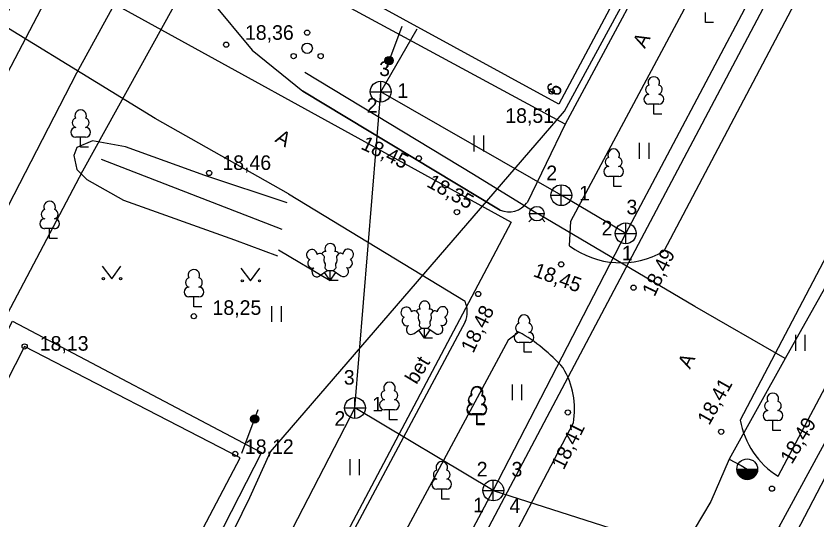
# Model space of a CAD drawing. Extents: x 713540 to 713867, y 6589774 to 6590061.
# Drawn here: x 713737.83 to 713776.25, y 6589992.37 to 6590016.58 of the extents above; entities that cross this region are included whole.
import ezdxf

# ---------------------------------------------------------------- set-up
doc = ezdxf.new("R2010")
doc.units = 0
for name, color, linetype in [('HALJASTUS', 7, 'Continuous'), ('HOONE', 7, 'Continuous'), ('HOONEDET', 7, 'Continuous'), ('KKAEV', 7, 'Continuous'), ('KORGUS', 7, 'Continuous'), ('KTRASS', 7, 'Continuous'), ('MPKAABEL', 7, 'Continuous'), ('PUU', 7, 'Continuous'), ('SIOHULIIN', 7, 'Continuous'), ('SITRASS', 7, 'Continuous'), ('TEE', 7, 'Continuous'), ('TORU NR', 7, 'Continuous'), ('TTRASS', 7, 'Continuous'), ('VKAEV', 7, 'Continuous'), ('VTRASS', 7, 'Continuous'), ('Слой 1', 7, 'Continuous')]:
    doc.layers.add(name, color=color, linetype=linetype)

msp = doc.modelspace()

# ---------------------------------------------------------------- linework, layer by layer
at = {"layer": 'HALJASTUS'}
for p, q in [((713759.827, 6590010.839), (713759.827, 6590010.078)), ((713760.282, 6590010.839), (713760.282, 6590010.078)), ((713767.765, 6590010.481), (713767.765, 6590009.72)), ((713768.22, 6590010.481), (713768.22, 6590009.72)), ((713741.967, 6590004.567), (713742.43, 6590003.96)), ((713742.43, 6590003.96), (713742.876, 6590004.567)), ((713748.637, 6590004.467), (713749.1, 6590003.86)), ((713749.1, 6590003.86), (713749.546, 6590004.467)), ((713750.106, 6590002.644), (713750.106, 6590001.883)), ((713750.561, 6590002.644), (713750.561, 6590001.883)), ((713775.264, 6590001.264), (713775.264, 6590000.503)), ((713775.719, 6590001.264), (713775.719, 6590000.503)), ((713761.657, 6589998.886), (713761.657, 6589998.125)), ((713762.112, 6589998.886), (713762.112, 6589998.125)), ((713753.865, 6589995.292), (713753.865, 6589994.531)), ((713754.32, 6589995.292), (713754.32, 6589994.531))]:
    msp.add_line(p, q, dxfattribs=at)
for points in [[(713741.51, 6590010.58), (713740.75, 6590010.26), (713740.61, 6590009.88), (713740.75, 6590009.21), (713741.23, 6590008.73), (713742.99, 6590007.73), (713748.33, 6590005.83), (713750.392, 6590005.054)], [(713750.851, 6590007.606), (713746.9, 6590008.92), (713743.09, 6590010.3), (713741.51, 6590010.58)], [(713750.621, 6590006.329), (713741.94, 6590009.69)], [(713750.444, 6590005.347), (713752.927, 6590003.875)]]:
    msp.add_lwpolyline(points, dxfattribs=at)
for centre, radius in [((713751.817, 6590015.778), 0.125), ((713751.817, 6590015.028), 0.25), ((713751.167, 6590014.653), 0.125), ((713752.467, 6590014.653), 0.125), ((713742.029, 6590003.96), 0.055), ((713742.858, 6590003.96), 0.055), ((713748.699, 6590003.86), 0.055), ((713749.528, 6590003.86), 0.055)]:
    msp.add_circle(centre, radius, dxfattribs=at)
at = {"layer": 'HOONE'}
for points in [[(713723.34, 6589972.07), (713723.61, 6589972.88), (713723.79, 6589973.29), (713724.07, 6589973.48), (713724.62, 6589973.75), (713731.173, 6589976.164), (713742.67, 6589980.4), (713749.07, 6589993.45), (713750.05, 6589995.65), (713764.17, 6590012), (713775.83, 6590033.48), (713771.45, 6590035.85), (713767.347, 6590038.074), (713765.461, 6590039.097), (713761.12, 6590041.45), (713760.38, 6590041.94), (713759.89, 6590042.09), (713754.46, 6590032.78), (713755.34, 6590032.31)], [(713759.88, 6590040.7), (713774.663, 6590032.532), (713763.899, 6590012.346), (713748.96, 6590020.53), (713759.88, 6590040.7)], [(713729.99, 6589999.65), (713748.41, 6590034.82)], [(713748.594, 6589995.354), (713738.24, 6590000.71), (713731.11, 6589986.72), (713741.204, 6589981.346), (713744.152, 6589986.933), (713744.399, 6589986.803), (713745.932, 6589989.695), (713745.679, 6589989.828), (713748.594, 6589995.354)]]:
    msp.add_lwpolyline(points, dxfattribs=at)
at = {"layer": 'HOONEDET'}
for points in [[(713764.214, 6590011.385), (713748.01, 6590020.15), (713748.17, 6590020.34), (713748.23, 6590020.65), (713753, 6590029.57)], [(713745.35, 6589987.248), (713741.618, 6589979.947), (713729.646, 6589986.262), (713737.66, 6590001.929), (713749.627, 6589995.616), (713745.981, 6589988.482)]]:
    msp.add_lwpolyline(points, dxfattribs=at)
at = {"layer": 'KKAEV'}
for p, q in [((713755.348, 6590012.443), (713755.348, 6590013.443)), ((713754.848, 6590012.943), (713755.848, 6590012.943)), ((713764.023, 6590007.47), (713764.023, 6590008.47)), ((713763.523, 6590007.97), (713764.523, 6590007.97)), ((713767.114, 6590005.64), (713767.114, 6590006.64)), ((713766.614, 6590006.14), (713767.614, 6590006.14)), ((713754.114, 6589997.254), (713754.114, 6589998.254)), ((713753.614, 6589997.754), (713754.614, 6589997.754)), ((713760.755, 6589993.294), (713760.755, 6589994.294)), ((713760.255, 6589993.794), (713761.255, 6589993.794))]:
    msp.add_line(p, q, dxfattribs=at)
for centre in [(713755.348, 6590012.943), (713764.023, 6590007.97), (713767.114, 6590006.14), (713754.114, 6589997.754), (713760.755, 6589993.794)]:
    msp.add_circle(centre, 0.5, dxfattribs=at)
at = {"layer": 'KORGUS'}
for centre in [(713747.93, 6590015.2), (713763.56, 6590012.95), (713757.18, 6590009.74), (713747.11, 6590009.04), (713759.01, 6590007.16), (713764.02, 6590004.65), (713767.49, 6590003.53), (713760.03, 6590003.23), (713746.37, 6590002.16), (713738.25, 6590000.71), (713764.34, 6589997.54), (713771.7, 6589996.61), (713748.36, 6589995.55), (713774.14, 6589993.88)]:
    msp.add_circle(centre, 0.125, dxfattribs=at)
at = {"layer": 'KTRASS'}
for p, q in [((713767.114, 6590006.14), (713787.107, 6590043.801)), ((713755.348, 6590012.943), (713757.104, 6590015.958)), ((713754.114, 6589997.754), (713755.348, 6590012.943)), ((713764.023, 6590007.97), (713755.348, 6590012.943)), ((713767.114, 6590006.14), (713764.023, 6590007.97)), ((713760.755, 6589993.794), (713767.114, 6590006.14)), ((713754.114, 6589997.754), (713749.216, 6589988.299)), ((713760.755, 6589993.794), (713754.114, 6589997.754)), ((713746.283, 6589966.793), (713760.755, 6589993.794)), ((713760.755, 6589993.794), (713773.086, 6589989.851))]:
    msp.add_line(p, q, dxfattribs=at)
at = {"layer": 'MPKAABEL'}
for points in [[(713796.776, 6590060.636), (713793.419, 6590054.295), (713774.719, 6590018.872), (713756.007, 6589983.478), (713738.52, 6589950.8), (713723.469, 6589921.84)], [(713734.86, 6589982.939), (713729.11, 6589985.97), (713735.68, 6589998.99), (713741.04, 6590009.14), (713752.51, 6590029.86)]]:
    msp.add_lwpolyline(points, dxfattribs=at)
at = {"layer": 'PUU'}
for p, q in [((713770.951, 6590016.264), (713770.951, 6590016.739)), ((713771.331, 6590016.264), (713770.951, 6590016.264)), ((713768.707, 6590012.342), (713768.227, 6590012.342)), ((713768.467, 6590011.867), (713768.467, 6590012.342)), ((713768.847, 6590011.867), (713768.467, 6590011.867)), ((713741.18, 6590010.755), (713740.7, 6590010.755)), ((713740.94, 6590010.28), (713740.94, 6590010.755)), ((713741.32, 6590010.28), (713740.94, 6590010.28)), ((713766.778, 6590008.869), (713766.298, 6590008.869)), ((713766.538, 6590008.394), (713766.538, 6590008.869)), ((713766.918, 6590008.394), (713766.538, 6590008.394)), ((713739.69, 6590006.365), (713739.21, 6590006.365)), ((713739.45, 6590005.89), (713739.45, 6590006.365)), ((713739.83, 6590005.89), (713739.45, 6590005.89)), ((713752.417, 6590004.095), (713752.777, 6590004.35)), ((713752.777, 6590004.35), (713753.072, 6590004.35)), ((713752.927, 6590003.875), (713752.927, 6590004.35)), ((713753.072, 6590004.35), (713753.432, 6590004.105)), ((713752.927, 6590003.875), (713752.652, 6590004.26)), ((713752.927, 6590003.875), (713753.197, 6590004.265)), ((713753.307, 6590003.875), (713752.927, 6590003.875)), ((713746.62, 6590003.085), (713746.14, 6590003.085)), ((713746.38, 6590002.61), (713746.38, 6590003.085)), ((713746.76, 6590002.61), (713746.38, 6590002.61)), ((713756.95, 6590001.329), (713757.31, 6590001.584)), ((713757.46, 6590001.109), (713757.185, 6590001.494)), ((713757.31, 6590001.584), (713757.605, 6590001.584)), ((713757.46, 6590001.109), (713757.46, 6590001.584)), ((713757.46, 6590001.109), (713757.73, 6590001.499)), ((713757.605, 6590001.584), (713757.965, 6590001.339)), ((713757.84, 6590001.109), (713757.46, 6590001.109)), ((713762.472, 6590000.902), (713761.992, 6590000.902)), ((713762.232, 6590000.427), (713762.232, 6590000.902)), ((713762.612, 6590000.427), (713762.232, 6590000.427)), ((713756.01, 6589997.665), (713755.53, 6589997.665)), ((713755.77, 6589997.19), (713755.77, 6589997.665)), ((713760.2, 6589997.425), (713759.72, 6589997.425)), ((713760.216, 6589997.47), (713759.736, 6589997.47)), ((713759.96, 6589996.95), (713759.96, 6589997.425)), ((713759.976, 6589996.995), (713759.976, 6589997.47)), ((713756.15, 6589997.19), (713755.77, 6589997.19)), ((713774.424, 6589997.15), (713773.944, 6589997.15)), ((713774.184, 6589996.675), (713774.184, 6589997.15)), ((713760.34, 6589996.95), (713759.96, 6589996.95)), ((713760.356, 6589996.995), (713759.976, 6589996.995)), ((713774.564, 6589996.675), (713774.184, 6589996.675)), ((713758.52, 6589993.854), (713758.04, 6589993.854)), ((713758.28, 6589993.379), (713758.28, 6589993.854)), ((713758.66, 6589993.379), (713758.28, 6589993.379))]:
    msp.add_line(p, q, dxfattribs=at)
for points in [[(713752.514, 6590005.162), (713752.617, 6590005.06), (713752.632, 6590005.03), (713752.632, 6590004.975), (713752.617, 6590004.885), (713752.617, 6590004.84), (713752.637, 6590004.76), (713752.677, 6590004.67), (713752.687, 6590004.625), (713752.682, 6590004.58), (713752.667, 6590004.515), (713752.667, 6590004.485), (713752.687, 6590004.445), (713752.712, 6590004.415), (713752.777, 6590004.35)], [(713753.331, 6590005.176), (713753.237, 6590005.06), (713753.222, 6590005.03), (713753.222, 6590004.975), (713753.237, 6590004.885), (713753.242, 6590004.84), (713753.222, 6590004.76), (713753.182, 6590004.67), (713753.172, 6590004.625), (713753.177, 6590004.58), (713753.192, 6590004.515), (713753.192, 6590004.485), (713753.172, 6590004.445), (713753.147, 6590004.415), (713753.077, 6590004.35)], [(713757.048, 6590002.396), (713757.15, 6590002.294), (713757.165, 6590002.264), (713757.165, 6590002.209), (713757.15, 6590002.119), (713757.15, 6590002.074), (713757.17, 6590001.994), (713757.21, 6590001.904), (713757.22, 6590001.859), (713757.215, 6590001.814), (713757.2, 6590001.749), (713757.2, 6590001.719), (713757.22, 6590001.679), (713757.245, 6590001.649), (713757.31, 6590001.584)], [(713757.864, 6590002.41), (713757.77, 6590002.294), (713757.755, 6590002.264), (713757.755, 6590002.209), (713757.77, 6590002.119), (713757.775, 6590002.074), (713757.755, 6590001.994), (713757.715, 6590001.904), (713757.705, 6590001.859), (713757.71, 6590001.814), (713757.725, 6590001.749), (713757.725, 6590001.719), (713757.705, 6590001.679), (713757.68, 6590001.649), (713757.61, 6590001.584)]]:
    msp.add_lwpolyline(points, dxfattribs=at)
for centre, radius, start, end in [((713768.467, 6590013.387), 0.277, 332.5799, 207.4201), ((713768.297, 6590013.039), 0.233, 109.0217, 253.1415), ((713768.637, 6590013.039), 0.233, 286.8508, 70.9859), ((713768.229, 6590012.579), 0.238, 90.0016, 269.3953), ((713768.704, 6590012.579), 0.238, 270.6047, 89.9984), ((713740.94, 6590011.8), 0.277, 332.5799, 207.4201), ((713740.77, 6590011.453), 0.233, 109.0217, 253.1415), ((713741.11, 6590011.453), 0.233, 286.8508, 70.9859), ((713740.703, 6590010.992), 0.238, 90.0016, 269.3953), ((713741.177, 6590010.992), 0.238, 270.6047, 89.9984), ((713766.538, 6590009.914), 0.277, 332.5799, 207.4201), ((713766.368, 6590009.567), 0.233, 109.0217, 253.1415), ((713766.708, 6590009.567), 0.233, 286.8508, 70.9859), ((713766.3, 6590009.107), 0.238, 90.0016, 269.3953), ((713766.775, 6590009.107), 0.238, 270.6047, 89.9984), ((713739.45, 6590007.41), 0.277, 332.5799, 207.4201), ((713739.28, 6590007.063), 0.233, 109.0217, 253.1415), ((713739.62, 6590007.063), 0.233, 286.8508, 70.9859), ((713739.213, 6590006.602), 0.238, 90.0016, 269.3953), ((713739.687, 6590006.602), 0.238, 270.6047, 89.9984), ((713752.927, 6590005.395), 0.256, 90.0013, 211.0159), ((713752.927, 6590005.395), 0.256, 328.9841, 89.9987), ((713752.043, 6590005.112), 0.256, 125.5389, 246.5536), ((713752.043, 6590005.112), 0.256, 4.5218, 125.5364), ((713752.43, 6590004.979), 0.202, 65.2382, 130.7412), ((713752.689, 6590005.063), 0.202, 84.7965, 150.2995), ((713753.164, 6590005.063), 0.202, 34.3857, 95.2035), ((713753.403, 6590004.988), 0.202, 50.3173, 111.1351), ((713753.787, 6590005.128), 0.256, 55.522, 176.5367), ((713753.787, 6590005.128), 0.256, 294.5049, 55.5195), ((713752.072, 6590004.695), 0.224, 125.4667, 288.5349), ((713753.767, 6590004.711), 0.224, 252.5235, 55.5918), ((713746.38, 6590004.13), 0.277, 332.5799, 207.4201), ((713752.281, 6590004.289), 0.237, 125.5377, 305.5366), ((713753.565, 6590004.301), 0.237, 235.5219, 55.5208), ((713746.21, 6590003.783), 0.233, 109.0217, 253.1415), ((713746.55, 6590003.783), 0.233, 286.8508, 70.9859), ((713746.143, 6590003.322), 0.238, 90.0016, 269.3953), ((713746.617, 6590003.322), 0.238, 270.6047, 89.9984), ((713757.46, 6590002.629), 0.256, 90.0013, 211.0159), ((713757.46, 6590002.629), 0.256, 328.9841, 89.9987), ((713756.577, 6590002.346), 0.256, 125.5389, 246.5536), ((713756.577, 6590002.346), 0.256, 4.5218, 125.5364), ((713756.963, 6590002.213), 0.202, 65.2382, 130.7412), ((713757.223, 6590002.296), 0.202, 84.7965, 150.2995), ((713757.698, 6590002.296), 0.202, 34.3857, 95.2035), ((713757.937, 6590002.222), 0.202, 50.3173, 111.1351), ((713758.321, 6590002.362), 0.256, 55.522, 176.5367), ((713758.321, 6590002.362), 0.256, 294.5049, 55.5195), ((713756.605, 6590001.928), 0.224, 125.4667, 288.5349), ((713758.3, 6590001.944), 0.224, 252.5235, 55.5918), ((713762.232, 6590001.947), 0.277, 332.5799, 207.4201), ((713756.814, 6590001.523), 0.237, 125.5377, 305.5366), ((713758.098, 6590001.535), 0.237, 235.5219, 55.5208), ((713762.062, 6590001.6), 0.233, 109.0217, 253.1415), ((713762.402, 6590001.6), 0.233, 286.8508, 70.9859), ((713761.995, 6590001.14), 0.238, 90.0016, 269.3953), ((713762.47, 6590001.14), 0.238, 270.6047, 89.9984), ((713755.77, 6589998.71), 0.277, 332.5799, 207.4201), ((713755.6, 6589998.363), 0.233, 109.0217, 253.1415), ((713755.94, 6589998.363), 0.233, 286.8508, 70.9859), ((713759.96, 6589998.47), 0.277, 332.5799, 207.4201), ((713759.976, 6589998.515), 0.277, 332.5799, 207.4201), ((713759.79, 6589998.123), 0.233, 109.0217, 253.1415), ((713759.806, 6589998.167), 0.233, 109.0217, 253.1415), ((713760.13, 6589998.123), 0.233, 286.8508, 70.9859), ((713760.146, 6589998.167), 0.233, 286.8508, 70.9859), ((713774.184, 6589998.195), 0.277, 332.5799, 207.4201), ((713755.533, 6589997.902), 0.238, 90.0016, 269.3953), ((713756.007, 6589997.902), 0.238, 270.6047, 89.9984), ((713759.723, 6589997.662), 0.238, 90.0016, 269.3953), ((713759.738, 6589997.707), 0.238, 90.0016, 269.3953), ((713760.197, 6589997.662), 0.238, 270.6047, 89.9984), ((713760.213, 6589997.707), 0.238, 270.6047, 89.9984), ((713774.014, 6589997.848), 0.233, 109.0217, 253.1415), ((713774.354, 6589997.848), 0.233, 286.8508, 70.9859), ((713773.947, 6589997.388), 0.238, 90.0016, 269.3953), ((713774.422, 6589997.388), 0.238, 270.6047, 89.9984), ((713758.28, 6589994.899), 0.277, 332.5799, 207.4201), ((713758.11, 6589994.552), 0.233, 109.0217, 253.1415), ((713758.45, 6589994.552), 0.233, 286.8508, 70.9859), ((713758.043, 6589994.092), 0.238, 90.0016, 269.3953), ((713758.518, 6589994.092), 0.238, 270.6047, 89.9984)]:
    msp.add_arc(centre, radius, start, end, dxfattribs=at)
at = {"layer": 'SIOHULIIN'}
for p, q in [((713756.364, 6590016.07), (713755.577, 6590013.972)), ((713748.682, 6589995.588), (713749.469, 6589997.686))]:
    msp.add_line(p, q, dxfattribs=at)
for centre, radius in [((713755.752, 6590014.437), 0.199), ((713755.752, 6590014.437), 0.19), ((713755.752, 6590014.437), 0.18), ((713755.752, 6590014.437), 0.171), ((713755.752, 6590014.437), 0.162), ((713755.752, 6590014.437), 0.152), ((713755.752, 6590014.437), 0.143), ((713755.752, 6590014.437), 0.133), ((713755.752, 6590014.437), 0.124), ((713755.752, 6590014.437), 0.114), ((713755.752, 6590014.437), 0.105), ((713755.752, 6590014.437), 0.0953), ((713755.752, 6590014.437), 0.0858), ((713755.752, 6590014.437), 0.0763), ((713755.752, 6590014.437), 0.0669), ((713755.752, 6590014.437), 0.0574), ((713755.752, 6590014.437), 0.0479), ((713755.752, 6590014.437), 0.0385), ((713755.752, 6590014.437), 0.029), ((713755.752, 6590014.437), 0.0195), ((713755.752, 6590014.437), 0.0101), ((713755.752, 6590014.437), 0.00061), ((713749.295, 6589997.222), 0.199), ((713749.295, 6589997.222), 0.19), ((713749.295, 6589997.222), 0.18), ((713749.295, 6589997.222), 0.171), ((713749.295, 6589997.222), 0.162), ((713749.295, 6589997.222), 0.152), ((713749.295, 6589997.222), 0.143), ((713749.295, 6589997.222), 0.133), ((713749.295, 6589997.222), 0.124), ((713749.295, 6589997.222), 0.114), ((713749.295, 6589997.222), 0.105), ((713749.295, 6589997.222), 0.0953), ((713749.295, 6589997.222), 0.0858), ((713749.295, 6589997.222), 0.0763), ((713749.295, 6589997.222), 0.0669), ((713749.295, 6589997.222), 0.0574), ((713749.295, 6589997.222), 0.0479), ((713749.295, 6589997.222), 0.0385), ((713749.295, 6589997.222), 0.029), ((713749.295, 6589997.222), 0.0195), ((713749.295, 6589997.222), 0.0101), ((713749.295, 6589997.222), 0.00061)]:
    msp.add_circle(centre, radius, dxfattribs=at)
at = {"layer": 'SITRASS'}
msp.add_lwpolyline([(713758.037, 6589957.335), (713761.879, 6589966.052), (713768.07, 6589978.18), (713774.37, 6589989.97), (713787.88, 6590015.87), (713811.74, 6590060.636)], dxfattribs=at)
at = {"layer": 'TEE'}
for points in [[(713750.927, 6590008.03), (713744.522, 6590011.657), (713734.435, 6590017.847), (713736.903, 6590022.368), (713743.125, 6590024.07), (713753.784, 6590044.184), (713757.249, 6590042.712), (713751.718, 6590032.993), (713753.469, 6590031.801), (713752.46, 6590029.762), (713751.314, 6590029.769), (713746.538, 6590021.024), (713746.409, 6590019.015), (713747.208, 6590017.314), (713749.179, 6590014.931), (713751.617, 6590012.967), (713761.092, 6590007.257)], [(713764.413, 6590005.547), (713764.486, 6590006.722), (713773.085, 6590022.835), (713783.408, 6590042.298)], [(713786.811, 6590039.201), (713779.489, 6590025.296), (713768.944, 6590005.279)], [(713792.829, 6590035.544), (713785.752, 6590022.212), (713772.613, 6589997.173)], [(713774.429, 6589994.473), (713796.161, 6590035.494)], [(713775.63, 6590032.655), (713764.214, 6590011.385), (713762.375, 6590007.609)], [(713761.092, 6590007.257), (713751.617, 6590012.967)], [(713750.927, 6590008.03), (713759.401, 6590002.879)], [(713759.411, 6590001.885), (713751.374, 6589986.858), (713750.166, 6589986.221), (713746.304, 6589988.311)], [(713761.987, 6590001.396), (713761.468, 6590001.011), (713752.66, 6589984.637)], [(713750.834, 6589971.193), (713761.766, 6589991.596), (713764.601, 6589997.036)]]:
    msp.add_lwpolyline(points, dxfattribs=at)
for centre, radius, start, end in [((713761.508, 6590008.255), 1.081, 247.3703, 323.2856), ((713766.882, 6590008.848), 4.122, 233.2053, 300.0107), ((713758.21, 6590002.369), 1.295, 338.0567, 23.1742), ((713758.276, 6589994.66), 7.691, 40.7145, 61.1472), ((713760.873, 6589997.703), 3.787, 349.8535, 31.4041), ((713776.602, 6589997.895), 4.054, 190.2638, 237.5847)]:
    msp.add_arc(centre, radius, start, end, dxfattribs=at)
at = {"layer": 'TTRASS'}
msp.add_lwpolyline([(713750, 6590030.71), (713740.74, 6590013.84), (713731.96, 6589996.83)], dxfattribs=at)
at = {"layer": 'VKAEV'}
for p, q in [((713762.499, 6590007.086), (713763.199, 6590007.086)), ((713762.602, 6590006.839), (713762.462, 6590006.699)), ((713763.096, 6590006.839), (713763.236, 6590006.699)), ((713772.451, 6589994.81), (713773.451, 6589994.81))]:
    msp.add_line(p, q, dxfattribs=at)
for centre, radius in [((713762.849, 6590007.086), 0.35), ((713772.951, 6589994.81), 0.5)]:
    msp.add_circle(centre, radius, dxfattribs=at)
for radius in [0.483, 0.468, 0.45, 0.435, 0.418, 0.403, 0.386, 0.371, 0.354, 0.339, 0.321, 0.306, 0.289, 0.274, 0.257, 0.242, 0.224, 0.209, 0.192, 0.177, 0.16, 0.145, 0.127, 0.112, 0.0951, 0.0801, 0.0628, 0.0478, 0.0328, 0.0178]:
    msp.add_arc((713772.951, 6589994.81), radius, 180, 0, dxfattribs=at)
at = {"layer": 'VTRASS'}
for points in [[(713786.9, 6590022.053), (713786.663, 6590021.42), (713779.918, 6590009.263), (713774.768, 6590000.13), (713772.089, 6589995.293), (713771.2, 6589993.262), (713769.595, 6589990.576), (713766.999, 6589985.749), (713760.969, 6589973.854), (713754.105, 6589960.72), (713753.933, 6589960.165), (713750.695, 6589954.533), (713746.011, 6589945.782), (713740.356, 6589934.918), (713733.16, 6589921.546), (713727.052, 6589912.116), (713721.352, 6589902.724), (713721.093, 6589902.329)], [(713774.768, 6590000.13), (713770.428, 6590002.625), (713762.925, 6590007.061), (713762.849, 6590007.086), (713759.809, 6590008.971), (713751.705, 6590013.861)], [(713772.089, 6589995.293), (713772.662, 6589994.986), (713772.949, 6589994.813)]]:
    msp.add_lwpolyline(points, dxfattribs=at)
at = {"layer": 'Слой 1'}
for points in [[(713800.41, 6589978.59), (713774.49, 6589992.04), (713800.2, 6590039.34), (713825.44, 6590025.65), (713821.32, 6590016.86), (713835.15, 6590009.97), (713817.82, 6589976.66), (713803.26, 6589984.22)], [(713738.74, 6590019.27), (713761.62, 6590006.68), (713742.5, 6589970.55), (713719.65, 6589982.59)]]:
    msp.add_lwpolyline(points, close=True, dxfattribs=at)

# ---------------------------------------------------------------- texts
at = {"layer": 'HOONE'}
msp.add_text('6', height=0.7, rotation=61.9613, dxfattribs=at).set_placement((713763.865, 6590012.664))
at = {"layer": 'HOONEDET'}
msp.add_text('bet', height=0.7, rotation=58.8475, dxfattribs=at).set_placement((713757.072, 6589998.846))
at = {"layer": 'KORGUS'}
for s, p in [('18,36', (713748.83, 6590015.435)), ('18,51', (713761.332, 6590011.445)), ('18,46', (713747.745, 6590009.185)), ('18,25', (713747.273, 6590002.225)), ('18,13', (713738.976, 6590000.505)), ('18,12', (713748.828, 6589995.545))]:
    msp.add_text(s, height=0.7, dxfattribs=at).set_placement(p)
for s, rotation, p in [('18,45', 334.644, (713754.351, 6590010.215)), ('18,35', 331.0598, (713757.513, 6590008.411)), ('18,49', 64.5257, (713768.498, 6590003.064)), ('18,45', 340.0148, (713762.629, 6590004.091)), ('18,48', 63.9338, (713759.791, 6590000.353)), ('18,41', 60.6795, (713771.123, 6589996.886)), ('18,49', 59.1084, (713775.093, 6589995.014)), ('18,41', 63.5985, (713764.137, 6589994.743))]:
    msp.add_text(s, height=0.7, rotation=rotation, dxfattribs=at).set_placement(p)
at = {"layer": 'TEE'}
for rotation, p in [(62.5477, (713768.034, 6590014.986)), (330.1728, (713750.234, 6590010.566)), (63.6334, (713770.2, 6589999.592))]:
    msp.add_text('A', height=0.7, rotation=rotation, dxfattribs=at).set_placement(p)
at = {"layer": 'TORU NR'}
for s, p in [('3', (713755.274, 6590013.695)), ('1', (713756.147, 6590012.643)), ('2', (713754.676, 6590011.932)), ('2', (713763.301, 6590008.692)), ('1', (713764.874, 6590007.721)), ('3', (713767.151, 6590007.053)), ('2', (713765.957, 6590006.038)), ('1', (713766.932, 6590004.844)), ('3', (713753.577, 6589998.875)), ('1', (713754.934, 6589997.585)), ('2', (713753.128, 6589996.897)), ('2', (713759.959, 6589994.465)), ('3', (713761.63, 6589994.465)), ('1', (713759.787, 6589992.745)), ('4', (713761.532, 6589992.708))]:
    msp.add_text(s, height=0.7, dxfattribs=at).set_placement(p)

doc.saveas('drawing.dxf')
